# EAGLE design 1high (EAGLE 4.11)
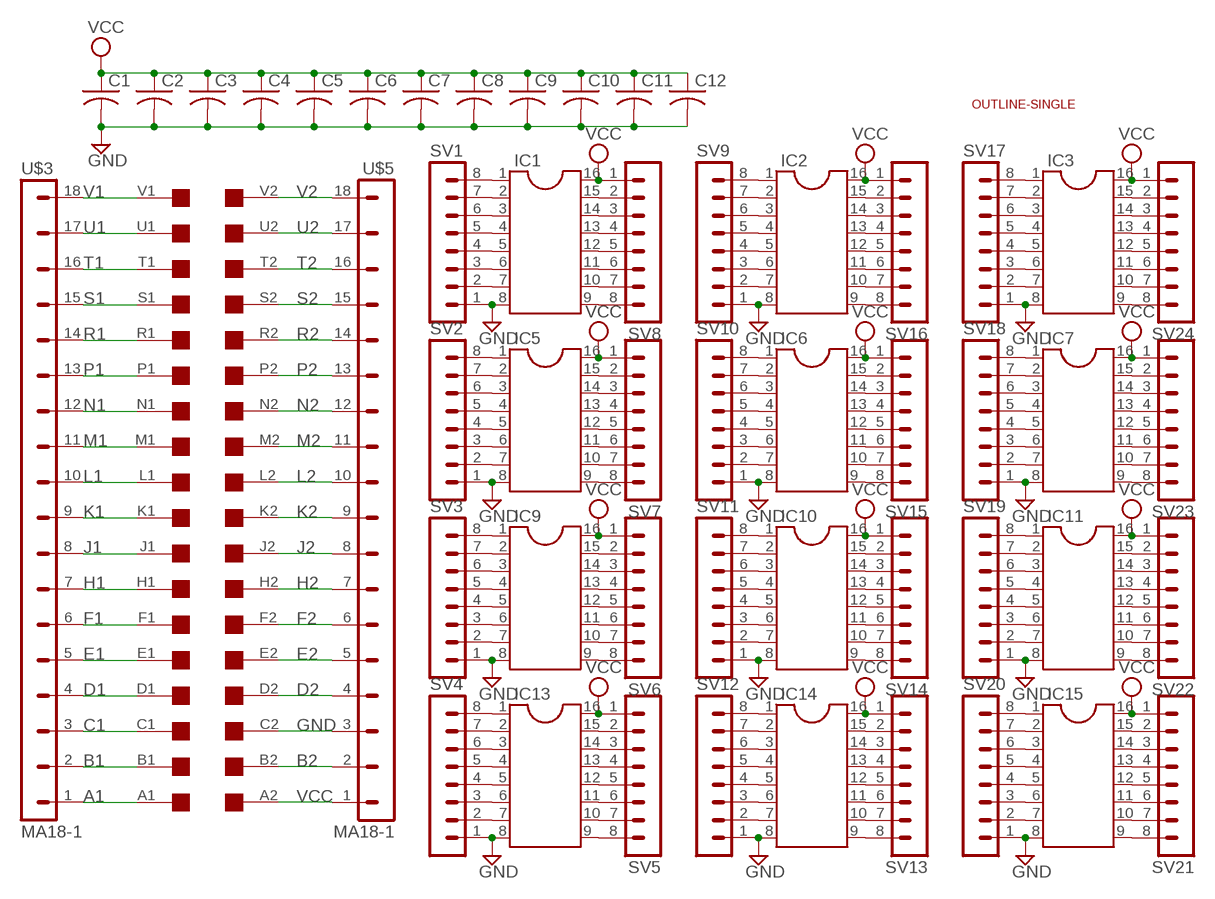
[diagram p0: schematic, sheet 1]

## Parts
C1  C-US050-025X075  [C050-025X075]
C2  C-US050-025X075  [C050-025X075]
C3  C-US050-025X075  [C050-025X075]
C4  C-US050-025X075  [C050-025X075]
C5  C-US050-025X075  [C050-025X075]
C6  C-US050-025X075  [C050-025X075]
C7  C-US050-025X075  [C050-025X075]
C8  C-US050-025X075  [C050-025X075]
C9  C-US050-025X075  [C050-025X075]
C10  C-US050-025X075  [C050-025X075]
C11  C-US050-025X075  [C050-025X075]
C12  C-US050-025X075  [C050-025X075]
IC1  DIL16  [DIL16]
IC2  DIL16  [DIL16]
IC3  DIL16  [DIL16]
IC5  DIL16  [DIL16]
IC6  DIL16  [DIL16]
IC7  DIL16  [DIL16]
IC9  DIL16  [DIL16]
IC10  DIL16  [DIL16]
IC11  DIL16  [DIL16]
IC13  DIL16  [DIL16]
IC14  DIL16  [DIL16]
IC15  DIL16  [DIL16]
SV1  MA08-1  [MA08-1]
SV2  MA08-1  [MA08-1]
SV3  MA08-1  [MA08-1]
SV4  MA08-1  [MA08-1]
SV5  MA08-1  [MA08-1]
SV6  MA08-1  [MA08-1]
SV7  MA08-1  [MA08-1]
SV8  MA08-1  [MA08-1]
SV9  MA08-1  [MA08-1]
SV10  MA08-1  [MA08-1]
SV11  MA08-1  [MA08-1]
SV12  MA08-1  [MA08-1]
SV13  MA08-1  [MA08-1]
SV14  MA08-1  [MA08-1]
SV15  MA08-1  [MA08-1]
SV16  MA08-1  [MA08-1]
SV17  MA08-1  [MA08-1]
SV18  MA08-1  [MA08-1]
SV19  MA08-1  [MA08-1]
SV20  MA08-1  [MA08-1]
SV21  MA08-1  [MA08-1]
SV22  MA08-1  [MA08-1]
SV23  MA08-1  [MA08-1]
SV24  MA08-1  [MA08-1]
U$2  OUTLINE-SINGLE  [SINGLE]
U$3  MA18-1  [MA18-1]
U$4  EDGE-2CONNECTOR  [EDGE-CON2]
U$5  MA18-1  [MA18-1]

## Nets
A1: U$3.1 U$4.A1
B1: U$3.2 U$4.B1
B2: U$4.B2 U$5.2
C1: U$3.3 U$4.C1
D1: U$3.4 U$4.D1
D2: U$4.D2 U$5.4
E1: U$3.5 U$4.E1
E2: U$4.E2 U$5.5
F1: U$3.6 U$4.F1
F2: U$4.F2 U$5.6
GND: C1.2 C2.2 C3.2 C4.2 C5.2 C6.2 C7.2 C8.2 C9.2 C10.2 C11.2 C12.2 IC1.8 IC2.8 IC3.8 IC5.8 IC6.8 IC7.8 IC9.8 IC10.8 IC11.8 IC13.8 IC14.8 IC15.8 SV1.1 SV2.1 SV3.1 SV4.1 SV9.1 SV10.1 SV11.1 SV12.1 SV17.1 SV18.1 SV19.1 SV20.1 U$4.C2 U$5.3
H1: U$3.7 U$4.H1
H2: U$4.H2 U$5.7
J1: U$3.8 U$4.J1
J2: U$4.J2 U$5.8
K1: U$3.9 U$4.K1
K2: U$4.K2 U$5.9
L1: U$3.10 U$4.L1
L2: U$4.L2 U$5.10
M1: U$3.11 U$4.M1
M2: U$4.M2 U$5.11
N1: U$3.12 U$4.N1
N2: U$4.N2 U$5.12
N$1: IC1.7 SV1.2
N$2: IC1.6 SV1.3
N$3: IC1.5 SV1.4
N$4: IC1.4 SV1.5
N$5: IC1.3 SV1.6
N$6: IC1.2 SV1.7
N$7: IC1.1 SV1.8
N$8: IC5.7 SV2.2
N$9: IC5.6 SV2.3
N$10: IC5.5 SV2.4
N$11: IC5.4 SV2.5
N$12: IC5.3 SV2.6
N$13: IC5.2 SV2.7
N$14: IC5.1 SV2.8
N$15: IC9.7 SV3.2
N$16: IC9.6 SV3.3
N$17: IC9.5 SV3.4
N$18: IC9.4 SV3.5
N$19: IC9.3 SV3.6
N$20: IC9.2 SV3.7
N$21: IC9.1 SV3.8
N$22: IC13.7 SV4.2
N$23: IC13.6 SV4.3
N$24: IC13.5 SV4.4
N$25: IC13.4 SV4.5
N$26: IC13.3 SV4.6
N$27: IC13.2 SV4.7
N$28: IC13.1 SV4.8
N$29: IC2.1 SV9.8
N$30: IC2.2 SV9.7
N$31: IC2.3 SV9.6
N$32: IC2.4 SV9.5
N$33: IC2.5 SV9.4
N$34: IC2.6 SV9.3
N$35: IC2.7 SV9.2
N$36: IC6.1 SV10.8
N$37: IC6.2 SV10.7
N$38: IC6.3 SV10.6
N$39: IC6.4 SV10.5
N$40: IC6.5 SV10.4
N$41: IC6.6 SV10.3
N$42: IC6.7 SV10.2
N$43: IC10.1 SV11.8
N$44: IC10.2 SV11.7
N$45: IC10.3 SV11.6
N$46: IC10.4 SV11.5
N$47: IC10.5 SV11.4
N$48: IC10.6 SV11.3
N$49: IC10.7 SV11.2
N$50: IC14.1 SV12.8
N$51: IC14.2 SV12.7
N$52: IC14.3 SV12.6
N$53: IC14.4 SV12.5
N$54: IC14.5 SV12.4
N$55: IC14.6 SV12.3
N$56: IC14.7 SV12.2
N$57: IC6.15 SV15.2
N$58: IC6.14 SV15.3
N$59: IC6.13 SV15.4
N$60: IC6.12 SV15.5
N$61: IC6.11 SV15.6
N$62: IC6.10 SV15.7
N$63: IC6.9 SV15.8
N$64: IC10.15 SV14.2
N$65: IC10.14 SV14.3
N$66: IC10.13 SV14.4
N$67: IC10.12 SV14.5
N$68: IC10.11 SV14.6
N$69: IC10.10 SV14.7
N$70: IC10.9 SV14.8
N$71: IC1.9 SV8.8
N$72: IC1.10 SV8.7
N$73: IC1.11 SV8.6
N$74: IC1.12 SV8.5
N$75: IC1.13 SV8.4
N$76: IC1.14 SV8.3
N$77: IC1.15 SV8.2
N$78: IC5.9 SV7.8
N$79: IC5.10 SV7.7
N$80: IC5.11 SV7.6
N$81: IC5.12 SV7.5
N$82: IC5.13 SV7.4
N$83: IC5.14 SV7.3
N$84: IC5.15 SV7.2
N$85: IC2.15 SV16.2
N$86: IC2.14 SV16.3
N$87: IC2.13 SV16.4
N$88: IC2.12 SV16.5
N$89: IC2.11 SV16.6
N$90: IC2.10 SV16.7
N$91: IC2.9 SV16.8
N$92: IC13.15 SV5.2
N$93: IC13.14 SV5.3
N$94: IC13.13 SV5.4
N$95: IC13.12 SV5.5
N$96: IC13.11 SV5.6
N$97: IC13.10 SV5.7
N$98: IC13.9 SV5.8
N$99: IC9.15 SV6.2
N$100: IC9.14 SV6.3
N$101: IC9.13 SV6.4
N$102: IC9.12 SV6.5
N$103: IC9.11 SV6.6
N$104: IC9.10 SV6.7
N$105: IC9.9 SV6.8
N$106: IC14.15 SV13.2
N$107: IC14.14 SV13.3
N$108: IC14.13 SV13.4
N$109: IC14.12 SV13.5
N$110: IC14.11 SV13.6
N$111: IC14.10 SV13.7
N$112: IC14.9 SV13.8
N$113: IC3.7 SV17.2
N$114: IC3.6 SV17.3
N$115: IC3.5 SV17.4
N$116: IC3.4 SV17.5
N$117: IC3.3 SV17.6
N$118: IC3.2 SV17.7
N$119: IC3.1 SV17.8
N$120: IC7.7 SV18.2
N$121: IC7.6 SV18.3
N$122: IC7.5 SV18.4
N$123: IC7.4 SV18.5
N$124: IC7.3 SV18.6
N$125: IC7.2 SV18.7
N$126: IC7.1 SV18.8
N$127: IC11.7 SV19.2
N$128: IC11.6 SV19.3
N$129: IC11.5 SV19.4
N$130: IC11.4 SV19.5
N$131: IC11.3 SV19.6
N$132: IC11.2 SV19.7
N$133: IC11.1 SV19.8
N$134: IC15.7 SV20.2
N$135: IC15.6 SV20.3
N$136: IC15.5 SV20.4
N$137: IC15.4 SV20.5
N$138: IC15.3 SV20.6
N$139: IC15.2 SV20.7
N$140: IC15.1 SV20.8
N$141: IC15.15 SV21.2
N$142: IC15.14 SV21.3
N$143: IC15.13 SV21.4
N$144: IC15.12 SV21.5
N$145: IC15.11 SV21.6
N$146: IC15.10 SV21.7
N$147: IC15.9 SV21.8
N$148: IC11.15 SV22.2
N$149: IC11.14 SV22.3
N$150: IC11.13 SV22.4
N$151: IC11.12 SV22.5
N$152: IC11.11 SV22.6
N$153: IC11.10 SV22.7
N$154: IC11.9 SV22.8
N$155: IC7.15 SV23.2
N$156: IC7.14 SV23.3
N$157: IC7.13 SV23.4
N$158: IC7.12 SV23.5
N$159: IC7.11 SV23.6
N$160: IC7.10 SV23.7
N$161: IC7.9 SV23.8
N$162: IC3.15 SV24.2
N$163: IC3.14 SV24.3
N$164: IC3.13 SV24.4
N$165: IC3.12 SV24.5
N$166: IC3.11 SV24.6
N$167: IC3.10 SV24.7
N$168: IC3.9 SV24.8
P1: U$3.13 U$4.P1
P2: U$4.P2 U$5.13
R1: U$3.14 U$4.R1
R2: U$4.R2 U$5.14
S1: U$3.15 U$4.S1
S2: U$4.S2 U$5.15
T1: U$3.16 U$4.T1
T2: U$4.T2 U$5.16
U1: U$3.17 U$4.U1
U2: U$4.U2 U$5.17
V1: U$3.18 U$4.V1
V2: U$4.V2 U$5.18
VCC: C1.1 C2.1 C3.1 C4.1 C5.1 C6.1 C7.1 C8.1 C9.1 C10.1 C11.1 C12.1 IC1.16 IC2.16 IC3.16 IC5.16 IC6.16 IC7.16 IC9.16 IC10.16 IC11.16 IC13.16 IC14.16 IC15.16 SV5.1 SV6.1 SV7.1 SV8.1 SV13.1 SV14.1 SV15.1 SV16.1 SV21.1 SV22.1 SV23.1 SV24.1 U$4.A2 U$5.1

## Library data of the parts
C1-C12 = rcl:C-US: CAPACITOR, American symbol
IC1-IC3 IC5-IC7 IC9-IC11 IC13-IC15 = ic-package:DIL16: Dual In Line
SV1-SV24 = con-lstb:MA08-1: PIN HEADER
U$2 = dec-con:OUTLINE-*: Board outlines for DEC boards.
U$3 U$5 = dec-con:MA18-1
U$4 = dec-con:EDGE-2: Double-Sided DEC edge connector.

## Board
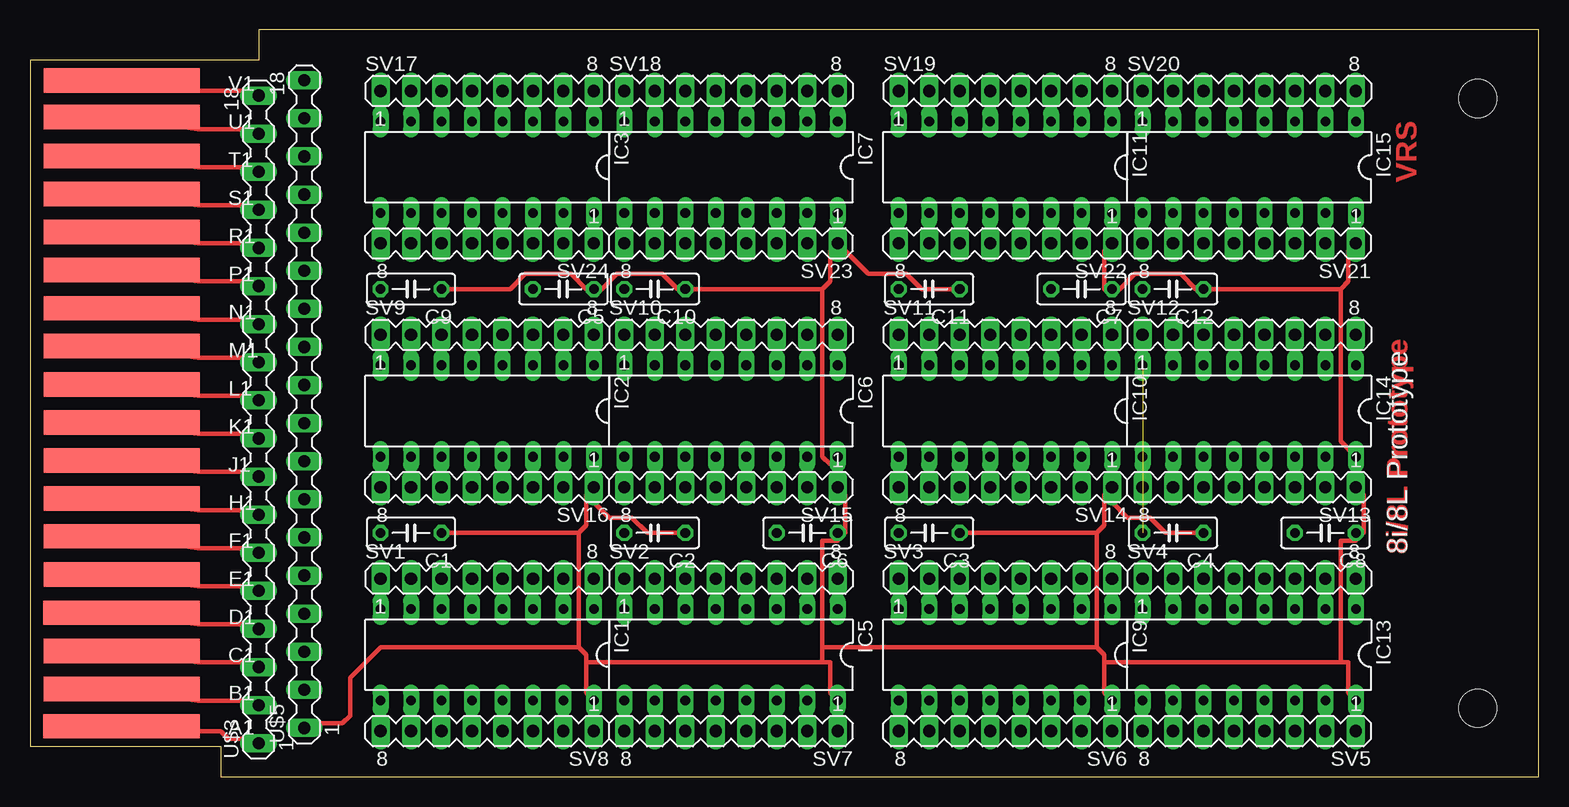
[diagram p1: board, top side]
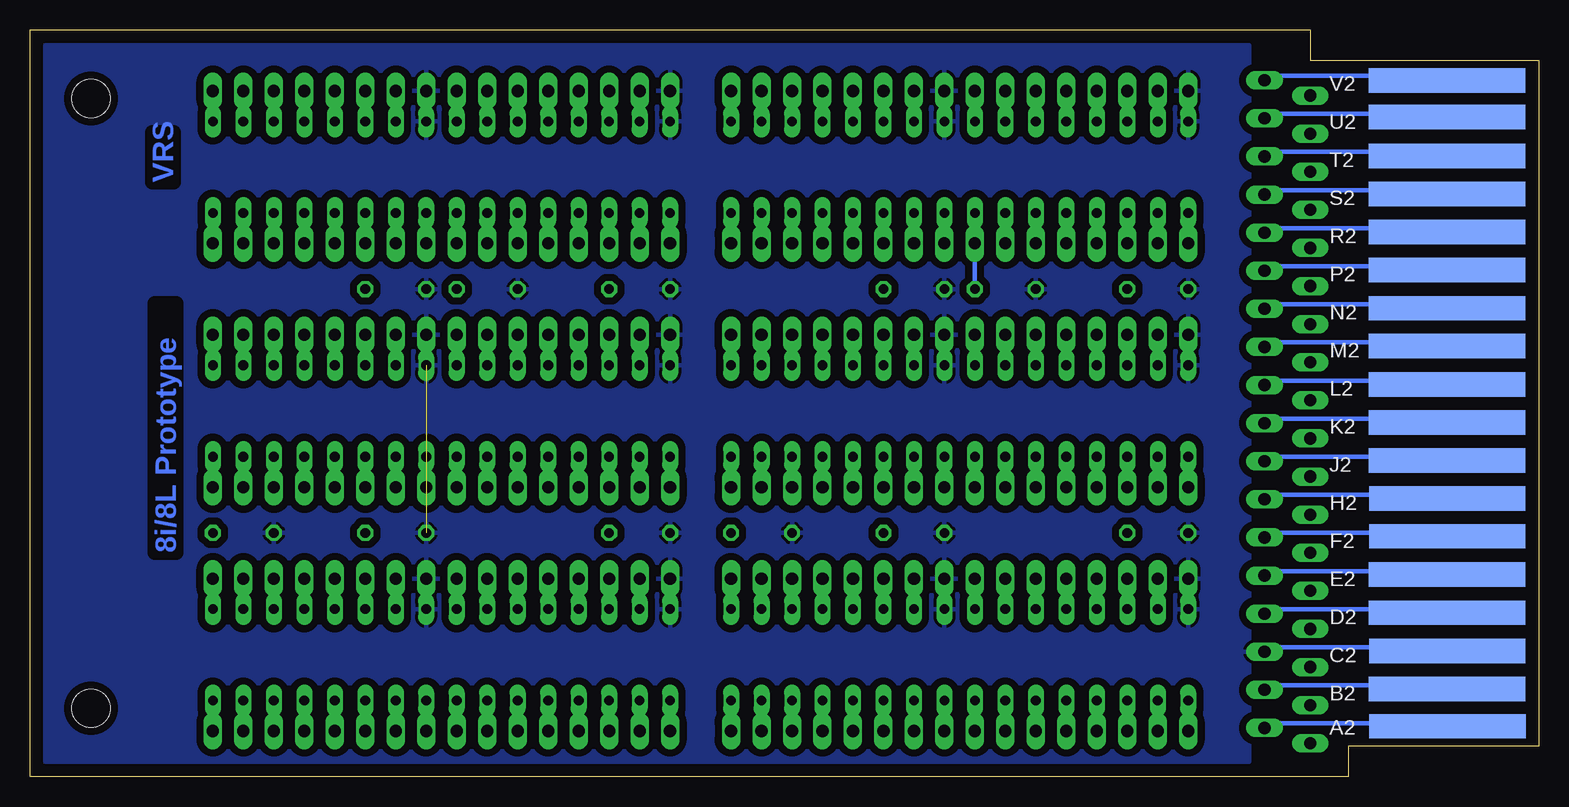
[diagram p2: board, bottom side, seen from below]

Size 125.73 x 62.23 mm. Coordinates in mm from the lower left corner, seen from the top.
Copper layers (1*16): Top 0.035mm / dielectric 1.5mm / Bottom 0.035mm
Design rules "olimex10mil": minimum track width 15mil, minimum drill 24mil, track to track 15mil, track to pad 10mil, pad to pad 10mil, via to via 10mil, smd to smd 10mil, copper to edge 25mil, drill to drill 10mil, minimum pad ring 10mil, minimum via ring 8mil, stop-mask expansion 0mil, vias tented up to drill 0mil, thermal gap 10mil

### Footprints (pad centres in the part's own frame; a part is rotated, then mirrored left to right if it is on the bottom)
C050-025X075 = drill 0.813 octagon: 1 -2.54,0; 2 2.54,0
DIL16 = drill 0.813 long: 1 -8.89,-3.81; 2 -6.35,-3.81; 3 -3.81,-3.81; 4 -1.27,-3.81; 5 1.27,-3.81; 6 3.81,-3.81; 7 6.35,-3.81; 8 8.89,-3.81; 9 8.89,3.81; 10 6.35,3.81; 11 3.81,3.81; 12 1.27,3.81; 13 -1.27,3.81; 14 -3.81,3.81; 15 -6.35,3.81; 16 -8.89,3.81
MA08-1 = drill 1.016 long: 1 -8.89,0; 2 -6.35,0; 3 -3.81,0; 4 -1.27,0; 5 1.27,0; 6 3.81,0; 7 6.35,0; 8 8.89,0
SINGLE = hole 3.175: 120.65,56.515; 120.65,5.715
MA18-1 = drill 1.016 long: 1 -25.146,0; 2 -21.971,0; 3 -18.796,0; 4 -15.621,0; 5 -12.446,0; 6 -9.271,0; 7 -6.096,0; 8 -2.921,0; 9 0.254,0; 10 3.429,0; 11 6.604,0; 12 9.779,0; 13 12.954,0; 14 16.129,0; 15 19.304,0; 16 22.479,0; 17 25.654,0; 18 28.829,0
EDGE-CON2 = smd 13.017 x 2.032: A1 7.633,4.207; B1 7.639,7.327; C1 7.636,10.489; D1 7.633,13.665; E1 7.642,16.84; F1 7.642,20.041; H1 7.642,23.19; J1 7.642,26.34; K1 7.642,29.515; L1 7.642,32.69; M1 7.642,35.89; N1 7.642,39.04; P1 7.642,42.24; R1 7.642,45.39; S1 7.642,48.565; T1 7.642,51.74; U1 7.642,54.966; V1 7.642,58.026 | smd 13.017 x 2.032 bottom: A2 7.614,4.207; B2 7.642,7.328; C2 7.617,10.49; D2 7.642,13.665; E2 7.642,16.84; F2 7.617,20.041; H2 7.617,23.19; J2 7.642,26.34; K2 7.642,29.515; L2 7.642,32.69; M2 7.642,35.89; N2 7.642,39.04; P2 7.642,42.24; R2 7.642,45.39; S2 7.642,48.565; T2 7.642,51.74; U2 7.642,54.966; V2 7.642,58.026

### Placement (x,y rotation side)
C1  31.75,20.32 180 top
C2  52.07,20.32 180 top
C3  74.93,20.32 180 top
C4  95.25,20.32 180 top
C5  44.45,40.64 180 top
C6  64.77,20.32 180 top
C7  87.63,40.64 180 top
C8  107.95,20.32 180 top
C9  31.75,40.64 180 top
C10  52.07,40.64 180 top
C11  74.93,40.64 180 top
C12  95.25,40.64 180 top
IC1  38.1,10.16 180 top
IC2  38.1,30.48 180 top
IC3  38.1,50.8 180 top
IC5  58.42,10.16 180 top
IC6  58.42,30.48 180 top
IC7  58.42,50.8 180 top
IC9  81.28,10.16 180 top
IC10  81.28,30.48 180 top
IC11  81.28,50.8 180 top
IC13  101.6,10.16 180 top
IC14  101.6,30.48 180 top
IC15  101.6,50.8 180 top
SV1  38.1,16.51 0 top
SV2  58.42,16.51 0 top
SV3  81.28,16.51 0 top
SV4  101.6,16.51 0 top
SV5  101.6,3.81 180 top
SV6  81.28,3.81 180 top
SV7  58.42,3.81 180 top
SV8  38.1,3.81 180 top
SV9  38.1,36.83 0 top
SV10  58.42,36.83 0 top
SV11  81.28,36.83 0 top
SV12  101.6,36.83 0 top
SV13  101.6,24.13 180 top
SV14  81.28,24.13 180 top
SV15  58.42,24.13 180 top
SV16  38.1,24.13 180 top
SV17  38.1,57.15 0 top
SV18  58.42,57.15 0 top
SV19  81.28,57.15 0 top
SV20  101.6,57.15 0 top
SV21  101.6,44.45 180 top
SV22  81.28,44.45 180 top
SV23  58.42,44.45 180 top
SV24  38.1,44.45 180 top
U$2  0,0 0 top
U$3  19.05,27.94 90 top
U$4  0,0 0 top
U$5  22.86,29.21 90 top

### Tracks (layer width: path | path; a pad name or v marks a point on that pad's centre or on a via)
A1
  Top 0.381: U$3.1 17.78,3.17 16.51,3.17 15.88,3.81 13.97,3.81 U$4.A1
B1
  Top 0.381: U$3.2 17.78,6.35 13.97,6.35 U$4.B1
B2
  Bottom 0.381: U$5.2 21.59,7.62 13.97,7.62 U$4.B2
C1
  Top 0.381: U$3.3 17.78,9.53 13.97,9.53 U$4.C1
D1
  Top 0.381: U$3.4 17.78,12.7 13.97,12.7 U$4.D1
D2
  Bottom 0.381: U$5.4 21.59,13.97 13.97,13.97 U$4.D2
E1
  Top 0.381: U$3.5 17.78,15.88 13.97,15.88 U$4.E1
E2
  Bottom 0.381: U$5.5 21.59,17.14 13.97,17.14 U$4.E2
F1
  Top 0.381: U$3.6 17.78,19.05 13.97,19.05 U$4.F1
F2
  Bottom 0.381: U$5.6 21.59,20.32 13.97,20.32 U$4.F2
GND  (1 unrouted)
  Bottom 0.381: 24.13,10.35 24.13,10.16 U$5.3 21.59,10.79 13.97,10.79 U$4.C2
  pour Bottom (isolate 0.61): 24.13,60.96 124.46,60.96 124.46,1.27 24.13,1.27
H1
  Top 0.381: U$3.7 17.78,22.23 13.97,22.23 U$4.H1
H2
  Bottom 0.381: U$5.7 21.59,23.5 13.97,23.5 U$4.H2
J1
  Top 0.381: U$3.8 17.78,25.4 13.97,25.4 U$4.J1
J2
  Bottom 0.381: U$5.8 21.59,26.67 13.97,26.67 U$4.J2
K1
  Top 0.381: U$3.9 17.78,28.57 13.97,28.57 U$4.K1
K2
  Bottom 0.381: U$5.9 21.59,29.84 13.97,29.84 U$4.K2
L1
  Top 0.381: U$3.10 17.78,31.75 13.97,31.75 U$4.L1
L2
  Bottom 0.381: U$5.10 21.59,33.02 13.97,33.02 U$4.L2
M1
  Top 0.381: U$3.11 17.78,34.92 13.97,34.92 U$4.M1
M2
  Bottom 0.381: U$5.11 21.59,36.2 13.97,36.2 U$4.M2
N1
  Top 0.381: U$3.12 17.78,38.1 13.97,38.1 U$4.N1
N2
  Bottom 0.381: U$5.12 21.59,39.37 13.97,39.37 U$4.N2
N$1
  Bottom 0.381: IC1.7 SV1.2
N$2
  Bottom 0.381: IC1.6 SV1.3
N$3
  Bottom 0.381: IC1.5 SV1.4
N$4
  Bottom 0.381: IC1.4 SV1.5
N$5
  Bottom 0.381: IC1.3 SV1.6
N$6
  Bottom 0.381: IC1.2 SV1.7
N$7
  Bottom 0.381: IC1.1 SV1.8
N$8
  Bottom 0.381: IC5.7 SV2.2
N$9
  Bottom 0.381: IC5.6 SV2.3
N$10
  Bottom 0.381: IC5.5 SV2.4
N$11
  Bottom 0.381: IC5.4 SV2.5
N$12
  Bottom 0.381: IC5.3 SV2.6
N$13
  Bottom 0.381: IC5.2 SV2.7
N$14
  Bottom 0.381: IC5.1 SV2.8
N$15
  Bottom 0.381: IC9.7 SV3.2
N$16
  Bottom 0.381: IC9.6 SV3.3
N$17
  Bottom 0.381: IC9.5 SV3.4
N$18
  Bottom 0.381: IC9.4 SV3.5
N$19
  Bottom 0.381: IC9.3 SV3.6
N$20
  Bottom 0.381: IC9.2 SV3.7
N$21
  Bottom 0.381: IC9.1 SV3.8
N$22
  Bottom 0.381: IC13.7 SV4.2
N$23
  Bottom 0.381: IC13.6 SV4.3
N$24
  Bottom 0.381: IC13.5 SV4.4
N$25
  Bottom 0.381: IC13.4 SV4.5
N$26
  Bottom 0.381: IC13.3 SV4.6
N$27
  Bottom 0.381: IC13.2 SV4.7
N$28
  Bottom 0.381: IC13.1 SV4.8
N$29
  Bottom 0.381: IC2.1 SV9.8
N$30
  Bottom 0.381: IC2.2 SV9.7
N$31
  Bottom 0.381: IC2.3 SV9.6
N$32
  Bottom 0.381: IC2.4 SV9.5
N$33
  Bottom 0.381: IC2.5 SV9.4
N$34
  Bottom 0.381: IC2.6 SV9.3
N$35
  Bottom 0.381: IC2.7 SV9.2
N$36
  Bottom 0.381: IC6.1 SV10.8
N$37
  Bottom 0.381: IC6.2 SV10.7
N$38
  Bottom 0.381: IC6.3 SV10.6
N$39
  Bottom 0.381: IC6.4 SV10.5
N$40
  Bottom 0.381: IC6.5 SV10.4
N$41
  Bottom 0.381: IC6.6 SV10.3
N$42
  Bottom 0.381: IC6.7 SV10.2
N$43
  Bottom 0.381: IC10.1 SV11.8
N$44
  Bottom 0.381: IC10.2 SV11.7
N$45
  Bottom 0.381: IC10.3 SV11.6
N$46
  Bottom 0.381: IC10.4 SV11.5
N$47
  Bottom 0.381: IC10.5 SV11.4
N$48
  Bottom 0.381: IC10.6 SV11.3
N$49
  Bottom 0.381: IC10.7 SV11.2
N$50
  Bottom 0.381: IC14.1 SV12.8
N$51
  Bottom 0.381: IC14.2 SV12.7
N$52
  Bottom 0.381: IC14.3 SV12.6
N$53
  Bottom 0.381: IC14.4 SV12.5
N$54
  Bottom 0.381: IC14.5 SV12.4
N$55
  Bottom 0.381: IC14.6 SV12.3
N$56
  Bottom 0.381: IC14.7 SV12.2
N$57
  Bottom 0.381: SV15.2 IC6.15
N$58
  Bottom 0.381: SV15.3 IC6.14
N$59
  Bottom 0.381: SV15.4 IC6.13
N$60
  Bottom 0.381: SV15.5 IC6.12
N$61
  Bottom 0.381: SV15.6 IC6.11
N$62
  Bottom 0.381: SV15.7 IC6.10
N$63
  Bottom 0.381: SV15.8 IC6.9
N$64
  Bottom 0.381: SV14.2 IC10.15
N$65
  Bottom 0.381: SV14.3 IC10.14
N$66
  Bottom 0.381: SV14.4 IC10.13
N$67
  Bottom 0.381: SV14.5 IC10.12
N$68
  Bottom 0.381: SV14.6 IC10.11
N$69
  Bottom 0.381: SV14.7 IC10.10
N$70
  Bottom 0.381: SV14.8 IC10.9
N$71
  Bottom 0.381: SV8.8 IC1.9
N$72
  Bottom 0.381: SV8.7 IC1.10
N$73
  Bottom 0.381: SV8.6 IC1.11
N$74
  Bottom 0.381: SV8.5 IC1.12
N$75
  Bottom 0.381: SV8.4 IC1.13
N$76
  Bottom 0.381: SV8.3 IC1.14
N$77
  Bottom 0.381: SV8.2 IC1.15
N$78
  Bottom 0.381: SV7.8 IC5.9
N$79
  Bottom 0.381: SV7.7 IC5.10
N$80
  Bottom 0.381: SV7.6 IC5.11
N$81
  Bottom 0.381: SV7.5 IC5.12
N$82
  Bottom 0.381: SV7.4 IC5.13
N$83
  Bottom 0.381: SV7.3 IC5.14
N$84
  Bottom 0.381: SV7.2 IC5.15
N$85
  Bottom 0.381: SV16.2 IC2.15
N$86
  Bottom 0.381: SV16.3 IC2.14
N$87
  Bottom 0.381: SV16.4 IC2.13
N$88
  Bottom 0.381: SV16.5 IC2.12
N$89
  Bottom 0.381: SV16.6 IC2.11
N$90
  Bottom 0.381: SV16.7 IC2.10
N$91
  Bottom 0.381: SV16.8 IC2.9
N$92
  Bottom 0.381: SV5.2 IC13.15
N$93
  Bottom 0.381: SV5.3 IC13.14
N$94
  Bottom 0.381: SV5.4 IC13.13
N$95
  Bottom 0.381: SV5.5 IC13.12
N$96
  Bottom 0.381: SV5.6 IC13.11
N$97
  Bottom 0.381: SV5.7 IC13.10
N$98
  Bottom 0.381: SV5.8 IC13.9
N$99
  Bottom 0.381: SV6.2 IC9.15
N$100
  Bottom 0.381: SV6.3 IC9.14
N$101
  Bottom 0.381: SV6.4 IC9.13
N$102
  Bottom 0.381: SV6.5 IC9.12
N$103
  Bottom 0.381: SV6.6 IC9.11
N$104
  Bottom 0.381: SV6.7 IC9.10
N$105
  Bottom 0.381: SV6.8 IC9.9
N$106
  Bottom 0.381: SV13.2 IC14.15
N$107
  Bottom 0.381: SV13.3 IC14.14
N$108
  Bottom 0.381: SV13.4 IC14.13
N$109
  Bottom 0.381: SV13.5 IC14.12
N$110
  Bottom 0.381: SV13.6 IC14.11
N$111
  Bottom 0.381: SV13.7 IC14.10
N$112
  Bottom 0.381: SV13.8 IC14.9
N$113
  Bottom 0.381: IC3.7 SV17.2
N$114
  Bottom 0.381: IC3.6 SV17.3
N$115
  Bottom 0.381: IC3.5 SV17.4
N$116
  Bottom 0.381: IC3.4 SV17.5
N$117
  Bottom 0.381: IC3.3 SV17.6
N$118
  Bottom 0.381: IC3.2 SV17.7
N$119
  Bottom 0.381: IC3.1 SV17.8
N$120
  Bottom 0.381: IC7.7 SV18.2
N$121
  Bottom 0.381: IC7.6 SV18.3
N$122
  Bottom 0.381: IC7.5 SV18.4
N$123
  Bottom 0.381: IC7.4 SV18.5
N$124
  Bottom 0.381: IC7.3 SV18.6
N$125
  Bottom 0.381: IC7.2 SV18.7
N$126
  Bottom 0.381: IC7.1 SV18.8
N$127
  Bottom 0.381: IC11.7 SV19.2
N$128
  Bottom 0.381: IC11.6 SV19.3
N$129
  Bottom 0.381: IC11.5 SV19.4
N$130
  Bottom 0.381: IC11.4 SV19.5
N$131
  Bottom 0.381: IC11.3 SV19.6
N$132
  Bottom 0.381: IC11.2 SV19.7
N$133
  Bottom 0.381: IC11.1 SV19.8
N$134
  Bottom 0.381: IC15.7 SV20.2
N$135
  Bottom 0.381: IC15.6 SV20.3
N$136
  Bottom 0.381: IC15.5 SV20.4
N$137
  Bottom 0.381: IC15.4 SV20.5
N$138
  Bottom 0.381: IC15.3 SV20.6
N$139
  Bottom 0.381: IC15.2 SV20.7
N$140
  Bottom 0.381: IC15.1 SV20.8
N$141
  Bottom 0.381: SV21.2 IC15.15
N$142
  Bottom 0.381: SV21.3 IC15.14
N$143
  Bottom 0.381: SV21.4 IC15.13
N$144
  Bottom 0.381: SV21.5 IC15.12
N$145
  Bottom 0.381: SV21.6 IC15.11
N$146
  Bottom 0.381: SV21.7 IC15.10
N$147
  Bottom 0.381: SV21.8 IC15.9
N$148
  Bottom 0.381: SV22.2 IC11.15
N$149
  Bottom 0.381: SV22.3 IC11.14
N$150
  Bottom 0.381: SV22.4 IC11.13
N$151
  Bottom 0.381: SV22.5 IC11.12
N$152
  Bottom 0.381: SV22.6 IC11.11
N$153
  Bottom 0.381: SV22.7 IC11.10
N$154
  Bottom 0.381: SV22.8 IC11.9
N$155
  Bottom 0.381: SV23.2 IC7.15
N$156
  Bottom 0.381: SV23.3 IC7.14
N$157
  Bottom 0.381: SV23.4 IC7.13
N$158
  Bottom 0.381: SV23.5 IC7.12
N$159
  Bottom 0.381: SV23.6 IC7.11
N$160
  Bottom 0.381: SV23.7 IC7.10
N$161
  Bottom 0.381: SV23.8 IC7.9
N$162
  Bottom 0.381: SV24.2 IC3.15
N$163
  Bottom 0.381: SV24.3 IC3.14
N$164
  Bottom 0.381: SV24.4 IC3.13
N$165
  Bottom 0.381: SV24.5 IC3.12
N$166
  Bottom 0.381: SV24.6 IC3.11
N$167
  Bottom 0.381: SV24.7 IC3.10
N$168
  Bottom 0.381: SV24.8 IC3.9
P1
  Top 0.381: U$3.13 17.78,41.27 13.97,41.27 U$4.P1
P2
  Bottom 0.381: U$5.13 21.59,42.55 13.97,42.55 U$4.P2
R1
  Top 0.381: U$3.14 17.78,44.45 13.97,44.45 U$4.R1
R2
  Bottom 0.381: U$5.14 21.59,45.72 13.97,45.72 U$4.R2
S1
  Top 0.381: U$3.15 17.78,47.62 13.97,47.62 U$4.S1
S2
  Bottom 0.381: U$5.15 21.59,48.9 13.97,48.9 U$4.S2
T1
  Top 0.381: U$3.16 17.78,50.8 13.97,50.8 U$4.T1
T2
  Bottom 0.381: U$5.16 21.59,52.07 13.97,52.07 U$4.T2
U1
  Top 0.381: U$3.17 17.78,53.98 13.97,53.98 U$4.U1
U2
  Bottom 0.381: U$5.17 21.59,55.24 13.97,55.24 U$4.U2
V1
  Top 0.381: U$3.18 17.78,57.15 13.97,57.15 U$4.V1
V2
  Bottom 0.381: U$5.18 21.59,58.42 13.97,58.42 U$4.V2
VCC
  Top 0.381: SV22.1 89.54,43.81 89.54,40.64 C7.1 90.81,40.64 92.08,41.91 95.89,41.91 97.16,40.64 C12.1 109.22,40.64 | 109.22,40.64 109.86,41.27 109.86,43.81 SV21.1 | SV13.1 111.13,23.5 111.13,20.32 C8.1 110.49,19.68 109.22,19.68 109.22,9.53 | 88.9,20.32 89.54,20.95 89.54,23.5 SV14.1 90.17,22.86 91.44,21.59 93.35,21.59 94.62,20.32 C4.1 | 88.9,20.32 C3.1 | 89.54,9.53 89.54,10.16 88.9,10.79 | 89.54,9.53 89.54,6.99 IC9.16 | 88.9,10.79 88.9,20.32 | 89.54,9.53 109.22,9.53 | 109.22,9.53 109.86,9.53 109.86,6.99 IC13.16 | 109.22,40.64 109.22,27.94 IC14.16 | C9.1 40.01,40.64 41.28,41.91 45.09,41.91 46.36,40.64 C5.1 47.63,40.64 48.9,41.91 52.71,41.91 53.98,40.64 C10.1 66.04,40.64 | 66.04,40.64 66.68,41.27 66.68,43.81 SV23.1 69.85,41.91 73.03,41.91 74.3,40.64 C11.1 | SV15.1 67.95,23.5 67.95,20.32 C6.1 67.31,19.68 66.04,19.68 66.04,10.79 | 45.72,20.32 46.36,20.95 46.36,23.5 SV16.1 46.99,22.86 48.26,21.59 50.17,21.59 51.44,20.32 C2.1 | 45.72,20.32 C1.1 | 46.36,9.53 46.36,10.16 45.72,10.79 | 46.36,9.53 46.36,6.99 IC1.16 | 45.72,10.79 45.72,20.32 | 46.36,9.53 66.04,9.53 | 66.04,9.53 66.68,9.53 66.68,6.99 IC5.16 | 66.04,9.53 66.04,10.79 | 45.72,10.79 29.21,10.79 26.67,8.26 26.67,5.08 26.04,4.45 24.13,4.45 U$5.1 | 66.04,40.64 66.04,26.67 66.68,26.04 IC6.16 | 66.04,10.79 88.9,10.79
  Bottom 0.381: SV22.1 IC11.16 | SV21.1 IC15.16 | SV13.1 IC14.16 | IC13.16 SV5.1 | IC9.16 SV6.1 | SV14.1 IC10.16 | IC3.16 SV24.1 C5.1 | SV23.1 IC7.16 | U$5.1 21.59,4.45 13.97,4.45 U$4.A2 | SV15.1 IC6.16 | IC5.16 SV7.1 | IC1.16 SV8.1 | SV16.1 IC2.16

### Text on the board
Top: VRS | 8i/8L Prototype
Bottom: VRS | 8i/8L Prototype
tPlace: 8i/8L Prototype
